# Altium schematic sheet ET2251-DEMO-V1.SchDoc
size A3
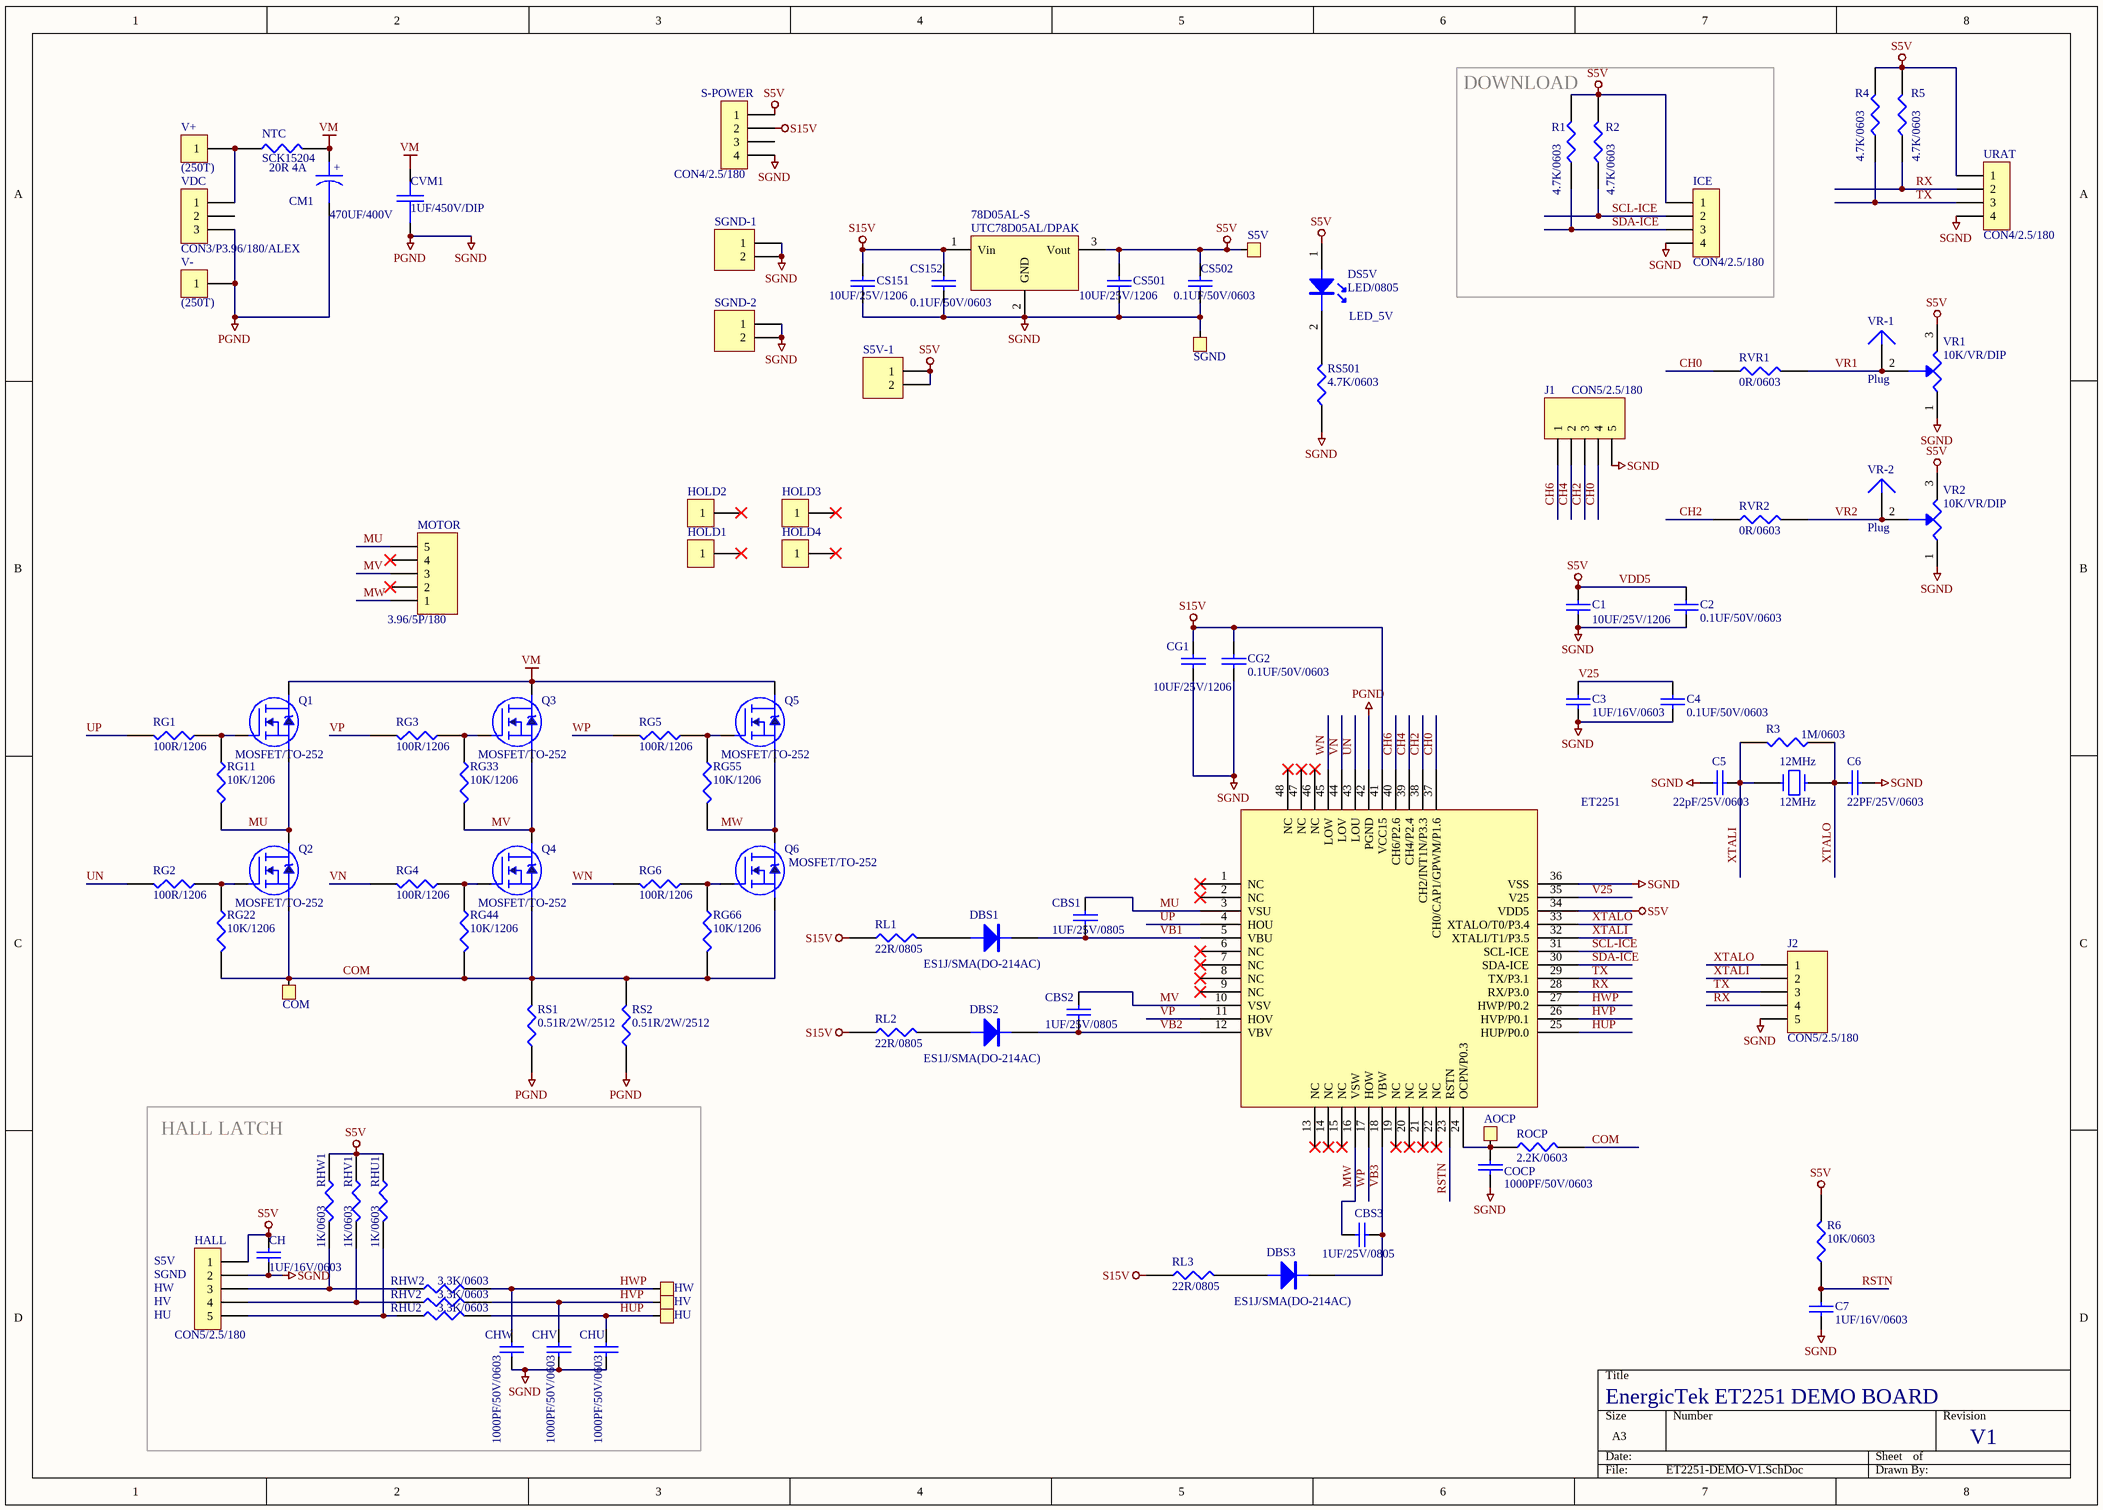
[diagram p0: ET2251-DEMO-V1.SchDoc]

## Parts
12MHz  12MHz  [XTAL-SMD]
78D05AL-S  UTC78D05AL/DPAK  [IC-7805-DPAK]
AOCP  (no value)  [TP-R-0.9mm]
C1  10UF/25V/1206  [C1206]
C2  0.1UF/50V/0603  [C0603]
C3  1UF/16V/0603  [C0603]
C4  0.1UF/50V/0603  [C0603]
C5  22pF/25V/0603  [C0603]
C6  22PF/25V/0603  [C0603]
C7  1UF/16V/0603  [C0603]
CBS1  1UF/25V/0805  [C0805]
CBS2  1UF/25V/0805  [C0805]
CBS3  1UF/25V/0805  [C0805]
CG1  10UF/25V/1206  [C1206]
CG2  0.1UF/50V/0603  [C0603]
CH  1UF/16V/0603  [C0603]
CHU  1000PF/50V/0603  [C0603]
CHV  1000PF/50V/0603  [C0603]
CHW  1000PF/50V/0603  [C0603]
CM1  470UF/400V  [C-30MM-10PITCH]
COCP  1000PF/50V/0603  [C0603]
COM  (no value)  [TP-R-0.9mm]
CS151  10UF/25V/1206  [C1206]
CS152  0.1UF/50V/0603  [C0603]
CS501  10UF/25V/1206  [C1206]
CS502  0.1UF/50V/0603  [C0603]
CVM1  1UF/450V/DIP  [C-18x7-P15]
DBS1  ES1J/SMA(DO-214AC)  [D-DO214AC-12]
DBS2  ES1J/SMA(DO-214AC)  [D-DO214AC-12]
DBS3  ES1J/SMA(DO-214AC)  [D-DO214AC-12]
DS5V  LED/0805  [LED-0805]
ET2251  ET2251  [IC-LQFP7x7-48]  (value not drawn)
HALL  (no value)  [CON-5P-2.5]
HOLD1  TP  [HOLD-3-6]  (value not drawn)
HOLD2  TP  [HOLD-3-6]  (value not drawn)
HOLD3  TP  [HOLD-3-6]  (value not drawn)
HOLD4  TP  [HOLD-3-6]  (value not drawn)
HU  (no value)  [TP-R-0.9mm]
HV  (no value)  [TP-R-0.9mm]
HW  (no value)  [TP-R-0.9mm]
ICE  CON4/2.5/180  [CON-4P-2.5]
J1  CON5/2.5/180  [HDR1X5]
J2  CON5/2.5/180  [HDR1X5]
MOTOR  Header 5  [CON-5-2P-3.96]  (value not drawn)
NTC  SCK15204  [11212005001]
Q1  MOSFET/TO-252  [TO-252]
Q2  MOSFET/TO-252  [TO-252]
Q3  MOSFET/TO-252  [TO-252]
Q4  MOSFET/TO-252  [TO-252]
Q5  MOSFET/TO-252  [TO-252]
Q6  MOSFET/TO-252  [TO-252]
R1  4.7K/0603  [R0603]
R2  4.7K/0603  [R0603]
R3  1M/0603  [R0603]
R4  4.7K/0603  [R0603]
R5  4.7K/0603  [R0603]
R6  10K/0603  [R0603]
RG1  100R/1206  [R1206]
RG2  100R/1206  [R1206]
RG3  100R/1206  [R1206]
RG4  100R/1206  [R1206]
RG5  100R/1206  [R1206]
RG6  100R/1206  [R1206]
RG11  10K/1206  [R1206]
RG22  10K/1206  [R1206]
RG33  10K/1206  [R1206]
RG44  10K/1206  [R1206]
RG55  10K/1206  [R1206]
RG66  10K/1206  [R1206]
RHU1  1K/0603  [R0603]
RHU2  3.3K/0603  [R0603]
RHV1  1K/0603  [R0603]
RHV2  3.3K/0603  [R0603]
RHW1  1K/0603  [R0603]
RHW2  3.3K/0603  [R0603]
RL1  22R/0805  [R0805]
RL2  22R/0805  [R0805]
RL3  22R/0805  [R0805]
ROCP  2.2K/0603  [R0603]
RS1  0.51R/2W/2512  [R2512]
RS2  0.51R/2W/2512  [R2512]
RS501  4.7K/0603  [R0603]
RVR1  0R/0603  [R0603]
RVR2  0R/0603  [R0603]
S5V  (no value)  [TP-R-0.9mm]
S5V-1  Header 2  [CON-SIP2]  (value not drawn)
S-POWER  CON4/2.5/180  [CON-4P-2.5]
SGND  (no value)  [TP-R-0.9mm]
SGND-1  Header 2  [CON-SIP2]  (value not drawn)
SGND-2  Header 2  [CON-SIP2]  (value not drawn)
URAT  CON4/2.5/180  [CON-4P-2.5]
V+  (250T)  [CON-P-850]
V-  (250T)  [CON-P-850]
VDC  CON3/P3.96/180/ALEX  [CON-3-1P-3.96]
VR1  10K/VR/DIP  [VR-6P-5.0]
VR2  10K/VR/DIP  [VR-6P-5.0]
VR-1  Plug  [PIN1]
VR-2  Plug  [PIN1]

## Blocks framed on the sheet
DOWNLOAD: ICE R1 R2
HALL LATCH: CH CHU CHV CHW HALL HU HV HW RHU1 RHU2 RHV1 RHV2 RHW1 RHW2

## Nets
PGND: 78D05AL-S.2(GND) C1.1 C2.1 C3.1 C4.1 C5.1 C6.1 C7.1 CG1.2 CG2.1 CH.1 CHU.2 CHV.2 CHW.2 CM1.2 COCP.2 CS151.1 CS152.2 CS501.1 CS502.2 CVM1.2 ET2251.36(VSS) ET2251.42(PGND) HALL.2 ICE.4 J1.5 J2.5 RS1.1 RS2.1 RS501.1 S-POWER.4 SGND.1 SGND-1.1 SGND-1.2 SGND-2.1 SGND-2.2 URAT.4 V-.1 VDC.3 VR1.1 VR2.1  [also labelled SGND]
S15V: 78D05AL-S.1(Vin) CG1.1 CG2.2 CS151.2 CS152.1 ET2251.41(VCC15) RL1.1 RL2.1 RL3.1 S-POWER.2
VDD5: 78D05AL-S.3(Vout) C1.2 C2.2 CH.2 CS501.2 CS502.1 DS5V.1 ET2251.34(VDD5) HALL.1 ICE.1 R1.2 R2.2 R4.2 R5.2 R6.2 RHU1.1 RHV1.1 RHW1.1 S5V.1 S5V-1.1 S5V-1.2 S-POWER.1 URAT.1 VR1.3 VR2.3  [also labelled S5V]
VM: CM1.1 CVM1.1 NTC.2 Q1.D Q3.D Q5.D
CH0: ET2251.37(CH0/CAP1/GPWM/P1.6) J1.4 RVR1.1
CH2: ET2251.38(CH2/INT1N/P3.3) J1.3 RVR2.1
CH4: ET2251.39(CH4/P2.4) J1.2
CH6: ET2251.40(CH6/P2.6) J1.1
COM: COM.1 Q2.S Q4.S Q6.S RG22.2 RG44.2 RG66.2 ROCP.2 RS1.2 RS2.2
HUP: CHU.1 ET2251.25(HUP/P0.0) HU.1 RHU2.2
HVP: CHV.1 ET2251.26(HVP/P0.1) HV.1 RHV2.2
HWP: CHW.1 ET2251.27(HWP/P0.2) HW.1 RHW2.2
MU: CBS1.1 ET2251.3(VSU) MOTOR.5 Q1.S Q2.D RG11.2
MV: CBS2.1 ET2251.10(VSV) MOTOR.3 Q3.S Q4.D RG33.2
MW: CBS3.1 ET2251.16(VSW) MOTOR.1 Q5.S Q6.D RG55.2
RSTN: C7.2 ET2251.23(RSTN) R6.1
RX: ET2251.28(RX/P3.0) J2.4 R5.1 URAT.2
SCL-ICE: ET2251.31(SCL-ICE) ICE.2 R2.1
SDA-ICE: ET2251.30(SDA-ICE) ICE.3 R1.1
TX: ET2251.29(TX/P3.1) J2.3 R4.1 URAT.3
UN: ET2251.43(LOU) RG2.2
UP: ET2251.4(HOU) RG1.2
V25: C3.2 C4.2 ET2251.35(V25)
VB1: CBS1.2 DBS1.2(K) ET2251.5(VBU)
VB2: CBS2.2 DBS2.2(K) ET2251.12(VBV)
VB3: CBS3.2 DBS3.2(K) ET2251.18(VBW)
VN: ET2251.44(LOV) RG4.2
VP: ET2251.11(HOV) RG3.2
VR1: RVR1.2 VR1.2 VR-1.1
VR2: RVR2.2 VR2.2 VR-2.1
WN: ET2251.45(LOW) RG6.2
WP: ET2251.17(HOW) RG5.2
XTALI: 12MHz.2 C5.2 ET2251.32(XTALI/T1/P3.5) J2.2 R3.1
XTALO: 12MHz.1 C6.2 ET2251.33(XTALO/T0/P3.4) J2.1 R3.2
NetAOCP_1: AOCP.1 COCP.1 ET2251.24(OCPN/P0.3) ROCP.1
NetDBS1_1: DBS1.1(A) RL1.2
NetDBS2_1: DBS2.1(A) RL2.2
NetDBS3_1: DBS3.1(A) RL3.2
NetDS5V_2: DS5V.2 RS501.2
NetHALL_3: HALL.3 RHW1.2 RHW2.1
NetHALL_4: HALL.4 RHV1.2 RHV2.1
NetHALL_5: HALL.5 RHU1.2 RHU2.1
NetNTC_1: NTC.1 V+.1 VDC.1
NetQ1_G: Q1.G RG1.1 RG11.1
NetQ2_G: Q2.G RG2.1 RG22.1
NetQ3_G: Q3.G RG3.1 RG33.1
NetQ4_G: Q4.G RG4.1 RG44.1
NetQ5_G: Q5.G RG5.1 RG55.1
NetQ6_G: Q6.G RG6.1 RG66.1

Not connected (* = marked no-connect by the designer): ET2251 1(NC)* 2(NC)* 6(NC)* 7(NC)* 8(NC)* 9(NC)* 13(NC)* 14(NC)* 15(NC)* 19(NC)* 20(NC)* 21(NC)* 22(NC)* 46(NC)* 47(NC)* 48(NC)*; HOLD1 1*; HOLD2 1*; HOLD3 1*; HOLD4 1*; MOTOR 2* 4*; S-POWER 3; VDC 2

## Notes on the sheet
- 20R 4A
- (near HALL) S5V
- (near HALL) SGND
- HW
- HV
- HU
- EnergicTek ET2251 DEMO BOARD
- V1

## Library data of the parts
12MHz = 12MHZ/H: HC-49S,12.000000MHz,+-30ppm,JXC,SMD,台興電子
AOCP COM HU HV HW S5V SGND = TEST POINT
C3 CH CHU CHV CHW = 0.1UF/50V/0603
C5 C7 = 18PF/25V/0603
C6 = 18PF/25V/0603: 18pF,25V,±5%,NPO,0603
CBS1-CBS3 = 1UF/25V/: 1uF(105),25V,±15%,X7R,0805,PSA(世愛)
CG1 = 10U: 晶片電容 10uF(106),25V,+/-10%,X5R,1206,世愛
CG2 = 0.1UF/50V/0603: 0.1uF(104)(100n),50V,±10%,X7R,0603,PSA; Text Field1: 11203410401-->0.1uF(104)(100n),  50V , -20+80% , Y5V , 0603
CM1 = 10UF/450V/10*20
COCP = 1000PF/50V/0603: 1000pF(102)(1n),50V,±10%,X7R,0603,PSA
DBS1-DBS3 = ES1J/SMA(DO-214A: ES1J , 600V , 1A , DO-214AC,富源;ES1J,600V,1A,DO-214AC,Lite-On
DS5V = LED-LC170JRCT/0805: LED RED, L-C170JRCT, SMD0805
HALL = CON5: Connector
HOLD1-HOLD4 V+ V- = CON1: Connector
ICE S-POWER URAT = CON4: Header 180度,CX-W2501-04,Pitch:2.5mm,4Pin,承洧
J1 J2 MOTOR = Header 5: Header, 5-Pin
NTC RL1-RL3 = RES1
Q1-Q6 = IRFR420: N-Channel MOSFET
R1 R2 R4 R5 RG1-RG6 RG11 RG22 RG33 RG44 RG55 RG66 = 5.1K/0603
R6 = 10K/0603: 10K,1%,0603,PSA
RHU1 RHU2 RHV1 RHV2 RHW1 RHW2 = 330R/0603
ROCP RVR1 RVR2 = 100R/0: 100R,1%,0603,PSA,世愛
RS1 RS2 = 0.51R/2W/2512: 0.51R,1%,2W,2512
S5V-1 SGND-1 SGND-2 = Header 2: Header, 2-Pin
VDC = CON3/P3.96/180/ALEX: 8673(180度),3Pin,Pitch:3.96,L:11.88mm*W:10.3mm*H:17.45mm,ALEX
VR1 VR2 = 10K/336: 3362W,10K(103),±10%,立式,DIP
